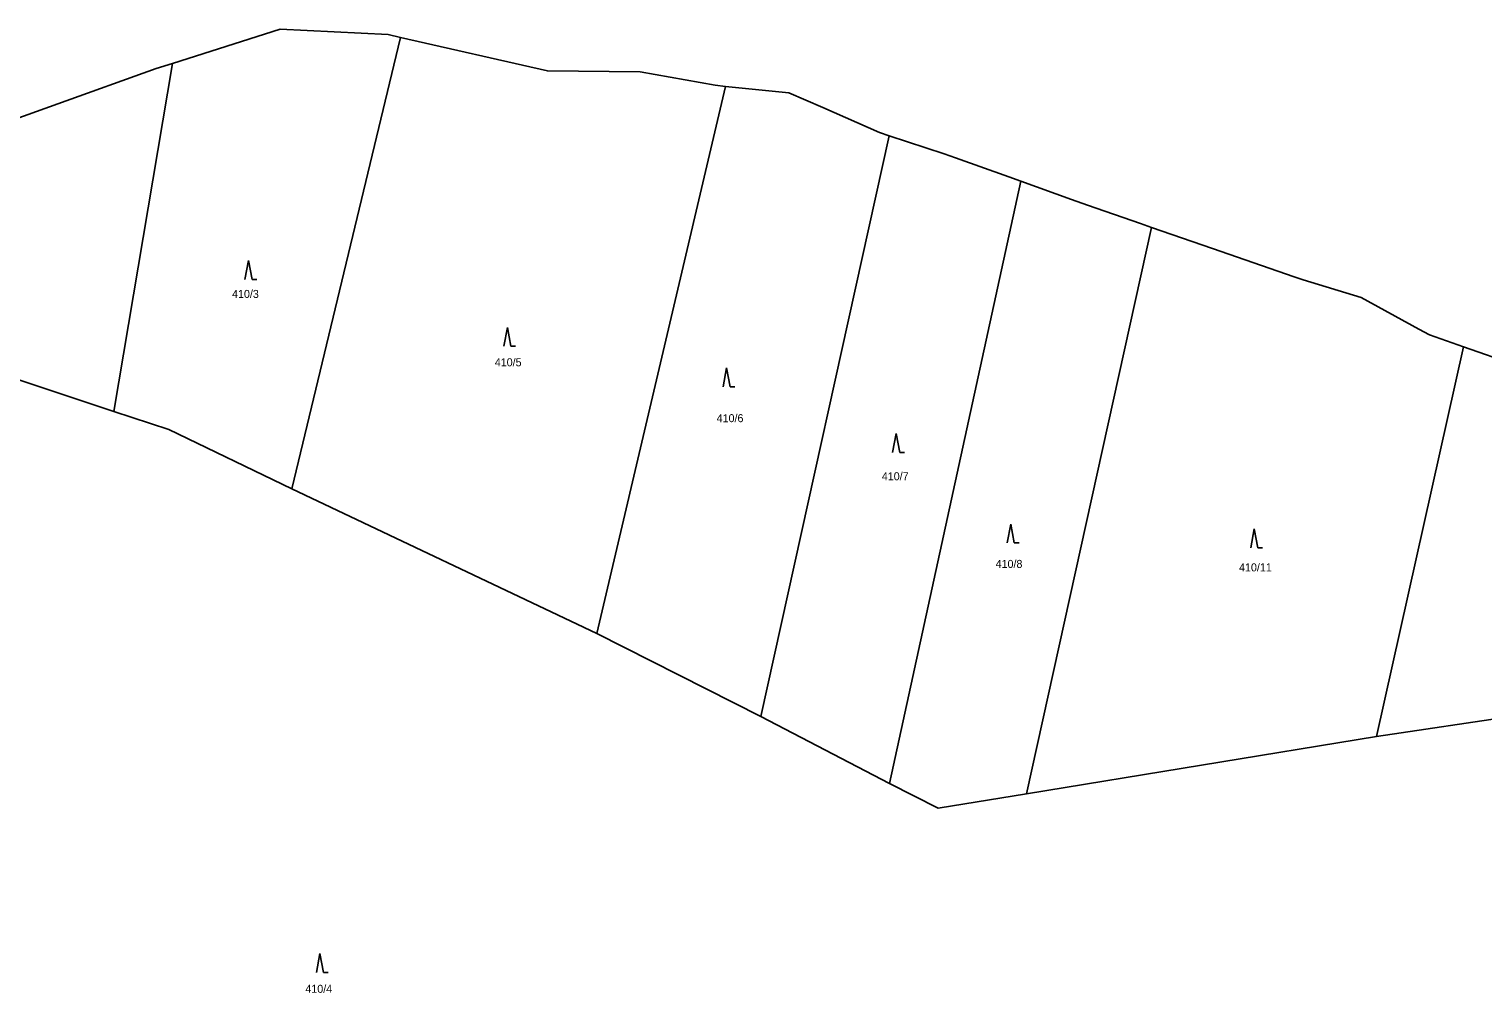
# Model space of a CAD drawing. Extents: x -744566 to -741843, y -1128407 to -1126744.
# Drawn here: x -744234.4 to -743925.6, y -1126948.6 to -1126743.9 of the extents above; entities that cross this region are included whole.
import ezdxf

# ---------------------------------------------------------------- set-up
doc = ezdxf.new("R2010")
doc.units = 0
for name, color, linetype in [('Hranice parcel', 7, 'Continuous'), ('Parcelní čísla', 7, 'Continuous'), ('Značky kultur', 7, 'Continuous')]:
    doc.layers.add(name, color=color, linetype=linetype)

msp = doc.modelspace()

# ---------------------------------------------------------------- linework, layer by layer
at = {"layer": 'Hranice parcel'}
for p, q in [((-744203.92, -1126751.24), (-744181.07, -1126743.95)), ((-744178.58, -1126841.61), (-744155.5, -1126745.73)), ((-744216.41, -1126825.15), (-744203.92, -1126751.24)), ((-744113.8, -1126872.27), (-744086.49, -1126756.12)), ((-744088.72, -1126755.89), (-744086.49, -1126756.12)), ((-744086.49, -1126756.12), (-744073.04, -1126757.49)), ((-744073.04, -1126757.49), (-744065.84, -1126760.63)), ((-744078.97, -1126889.91), (-744051.72, -1126766.6)), ((-744051.64, -1126904.14), (-744023.75, -1126776.28)), ((-744022.58, -1126906.37), (-743995.98, -1126786.07)), ((-744315.54, -1126792.12), (-744216.41, -1126825.15)), ((-743948.2, -1126894.15), (-743929.77, -1126811.42)), ((-744113.8, -1126872.27), (-744178.58, -1126841.61)), ((-744078.97, -1126889.91), (-744113.8, -1126872.27)), ((-743895.01, -1126886.33), (-743948.2, -1126894.15)), ((-744051.64, -1126904.14), (-744078.97, -1126889.91)), ((-743948.2, -1126894.15), (-744022.58, -1126906.37))]:
    msp.add_line(p, q, dxfattribs=at)
for points in [[(-744181.07, -1126743.95), (-744158.13, -1126745.13), (-744155.5, -1126745.73)], [(-744155.5, -1126745.73), (-744124.33, -1126752.85), (-744104.6, -1126753.06), (-744088.72, -1126755.89)], [(-744315.54, -1126792.12), (-744297.73, -1126782.66), (-744282.53, -1126776.08), (-744249.22, -1126767.3), (-744207.42, -1126752.3), (-744203.92, -1126751.24)], [(-744065.84, -1126760.63), (-744053.76, -1126765.92), (-744051.72, -1126766.6)], [(-744051.72, -1126766.6), (-744040.06, -1126770.46), (-744038.85, -1126770.88)], [(-744038.85, -1126770.88), (-744037.64, -1126771.28), (-744026.31, -1126775.35), (-744023.75, -1126776.28)], [(-744023.75, -1126776.28), (-744012.99, -1126780.15), (-744009.61, -1126781.37), (-743998.36, -1126785.25), (-743995.98, -1126786.07)], [(-743995.98, -1126786.07), (-743983.03, -1126790.54), (-743965.68, -1126796.53), (-743963.77, -1126797.19), (-743951.47, -1126800.96), (-743939.23, -1126807.68), (-743937, -1126808.91), (-743929.77, -1126811.42)], [(-743929.77, -1126811.42), (-743918.76, -1126815.23), (-743911.47, -1126816.19), (-743884.23, -1126821.23)], [(-744216.41, -1126825.15), (-744204.75, -1126828.97), (-744178.58, -1126841.61)], [(-744022.58, -1126906.37), (-744041.32, -1126909.37), (-744051.64, -1126904.14)]]:
    msp.add_lwpolyline(points, dxfattribs=at)
at = {"layer": 'Značky kultur'}
for p, q in [((-744187.8, -1126793.12), (-744188.55, -1126797.12)), ((-744187.05, -1126797.12), (-744187.8, -1126793.12)), ((-744187.05, -1126797.12), (-744186.054, -1126797.12)), ((-744132.81, -1126807.31), (-744133.56, -1126811.31)), ((-744132.06, -1126811.31), (-744132.81, -1126807.31)), ((-744132.06, -1126811.31), (-744131.064, -1126811.31)), ((-744086.25, -1126815.92), (-744087, -1126819.92)), ((-744085.5, -1126819.92), (-744086.25, -1126815.92)), ((-744085.5, -1126819.92), (-744084.504, -1126819.92)), ((-744050.24, -1126829.85), (-744050.99, -1126833.85)), ((-744049.49, -1126833.85), (-744050.24, -1126829.85)), ((-744049.49, -1126833.85), (-744048.494, -1126833.85)), ((-744025.9, -1126849.05), (-744026.65, -1126853.05)), ((-744025.15, -1126853.05), (-744025.9, -1126849.05)), ((-743974.2, -1126850.09), (-743974.95, -1126854.09)), ((-743973.45, -1126854.09), (-743974.2, -1126850.09)), ((-744025.15, -1126853.05), (-744024.154, -1126853.05)), ((-743973.45, -1126854.09), (-743972.454, -1126854.09)), ((-744172.63, -1126940.27), (-744173.38, -1126944.27)), ((-744171.88, -1126944.27), (-744172.63, -1126940.27)), ((-744171.88, -1126944.27), (-744170.884, -1126944.27))]:
    msp.add_line(p, q, dxfattribs=at)

# ---------------------------------------------------------------- texts
at = {"layer": 'Parcelní čísla'}
for s, p in [('410/3', (-744191.29, -1126801.04)), ('410/5', (-744135.49, -1126815.56)), ('410/6', (-744088.37, -1126827.43)), ('410/7', (-744053.29, -1126839.76)), ('410/8', (-744029.12, -1126858.37)), ('410/11', (-743977.42, -1126859.11)), ('410/4', (-744175.72, -1126948.6))]:
    msp.add_text(s, height=1.7, dxfattribs=at).set_placement(p)

doc.saveas('drawing.dxf')
